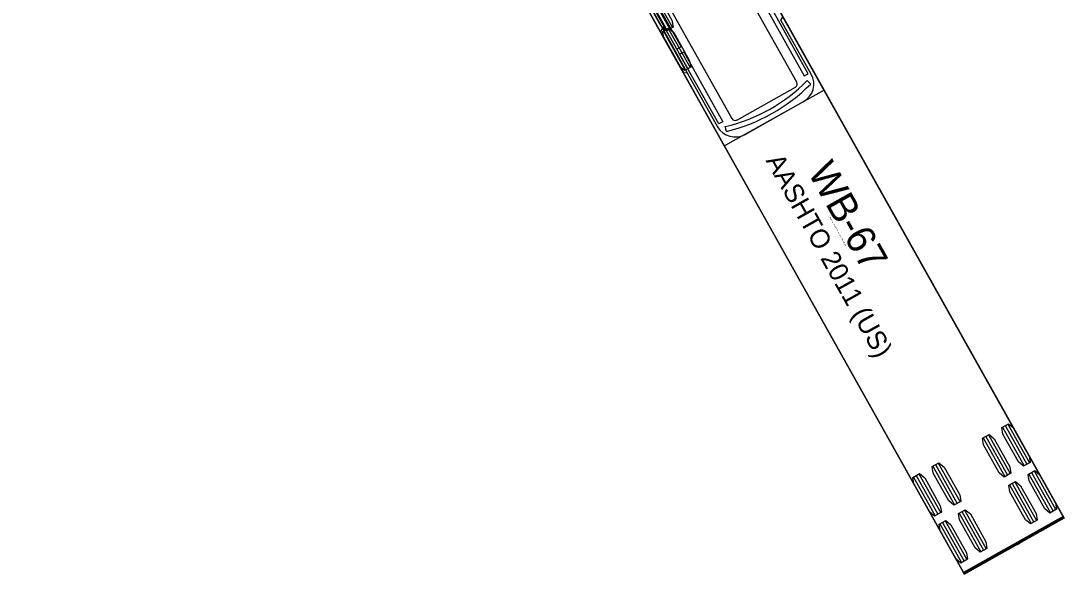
# Model space of a CAD drawing. Extents: x 1639988 to 1641860, y 841974 to 844187.
# Drawn here: x 1640559 to 1640636.6, y 843315.2 to 843356.3 of the extents above; entities that cross this region are included whole.
import ezdxf

# ---------------------------------------------------------------- set-up
doc = ezdxf.new("R2010")
doc.units = 0
for name, color, linetype in [('Scratch_Level_1', 7, 'Continuous'), ('Scratch_Level_2', 7, 'Continuous'), ('Scratch_Level_3', 7, 'Continuous'), ('Scratch_Level_4', 7, 'Continuous'), ('Scratch_Level_5', 7, 'Continuous'), ('Scratch_Level_6', 7, 'Continuous')]:
    doc.layers.add(name, color=color, linetype=linetype)

msp = doc.modelspace()

# ---------------------------------------------------------------- linework, layer by layer
at = {"layer": 'Scratch_Level_1'}
for p, q in [((1640605.299, 843358.802), (1640607.093, 843355.604)), ((1640605.499, 843358.914), (1640607.293, 843355.717)), ((1640605.699, 843359.026), (1640607.493, 843355.829)), ((1640632.043, 843326.126), (1640633.658, 843323.248)), ((1640632.243, 843326.238), (1640633.857, 843323.36)), ((1640632.442, 843326.35), (1640634.057, 843323.472)), ((1640630.604, 843325.319), (1640632.219, 843322.441)), ((1640630.804, 843325.431), (1640632.418, 843322.553)), ((1640631.003, 843325.543), (1640632.618, 843322.665)), ((1640626.868, 843323.223), (1640628.483, 843320.345)), ((1640627.068, 843323.335), (1640628.683, 843320.457)), ((1640627.268, 843323.447), (1640628.883, 843320.569)), ((1640634.2, 843322.75), (1640635.815, 843319.872)), ((1640634.4, 843322.862), (1640636.015, 843319.984)), ((1640625.429, 843322.415), (1640627.044, 843319.537)), ((1640625.629, 843322.527), (1640627.244, 843319.649)), ((1640625.829, 843322.639), (1640627.444, 843319.762)), ((1640632.961, 843322.055), (1640634.576, 843319.177)), ((1640634, 843322.638), (1640635.615, 843319.76)), ((1640632.561, 843321.83), (1640634.176, 843318.952)), ((1640632.761, 843321.942), (1640634.376, 843319.064)), ((1640628.826, 843319.734), (1640630.44, 843316.856)), ((1640629.026, 843319.846), (1640630.64, 843316.968)), ((1640629.225, 843319.959), (1640630.84, 843317.081)), ((1640627.387, 843318.927), (1640629.002, 843316.049)), ((1640627.587, 843319.039), (1640629.201, 843316.161)), ((1640627.786, 843319.151), (1640629.401, 843316.273)), ((1640636.561, 843319.478), (1640629.149, 843315.319)), ((1640632.889, 843317.337), (1640632.855, 843317.398)), ((1640633.353, 843317.597), (1640633.121, 843317.467)), ((1640632.658, 843317.207), (1640632.426, 843317.077))]:
    msp.add_line(p, q, dxfattribs=at)
for points in [[(1640569.35, 843442.491), (1640571.641, 843437.743), (1640573.976, 843433.013), (1640576.351, 843428.298), (1640578.765, 843423.598), (1640581.214, 843418.911), (1640583.696, 843414.235), (1640586.206, 843409.569), (1640588.742, 843404.91), (1640593.874, 843395.608), (1640599.062, 843386.314), (1640636.63, 843319.355), (1640629.218, 843315.196), (1640629.14, 843315.333), (1640629.14, 843315.333)], [(1640629.14, 843315.333), (1640571.712, 843417.686), (1640569.11, 843422.364), (1640566.534, 843427.059), (1640563.994, 843431.777), (1640560.226, 843438.882)], [(1640636.576, 843319.405), (1640636.595, 843319.416), (1640636.561, 843319.478), (1640633.788, 843324.42), (1640610.695, 843365.576), (1640606.989, 843363.496), (1640603.283, 843361.416), (1640626.375, 843320.261), (1640629.149, 843315.319), (1640629.184, 843315.257), (1640629.203, 843315.268)], [(1640633.153, 843317.404), (1640633.386, 843317.534), (1640633.387, 843317.536), (1640633.353, 843317.597), (1640633.384, 843317.614), (1640636.554, 843319.393), (1640636.555, 843319.394)], [(1640632.664, 843317.21), (1640633.118, 843317.465)], [(1640629.224, 843315.28), (1640629.224, 843315.28), (1640632.395, 843317.059), (1640632.426, 843317.077), (1640632.46, 843317.016), (1640632.462, 843317.016), (1640632.695, 843317.147)]]:
    msp.add_lwpolyline(points, dxfattribs=at)
for points in [[(1640605.249, 843358.774), (1640605.748, 843359.054), (1640606.15, 843358.691), (1640607.442, 843356.388), (1640607.542, 843355.856), (1640607.044, 843355.577), (1640606.642, 843355.94), (1640605.35, 843358.242)], [(1640631.993, 843326.098), (1640632.492, 843326.378), (1640632.868, 843326.06), (1640634.031, 843323.987), (1640634.107, 843323.5), (1640633.608, 843323.22), (1640633.232, 843323.539), (1640632.069, 843325.611)], [(1640630.554, 843325.291), (1640631.053, 843325.571), (1640631.429, 843325.252), (1640632.592, 843323.18), (1640632.668, 843322.693), (1640632.169, 843322.413), (1640631.793, 843322.731), (1640630.63, 843324.804)], [(1640626.819, 843323.195), (1640627.318, 843323.475), (1640627.694, 843323.156), (1640628.857, 843321.084), (1640628.932, 843320.597), (1640628.434, 843320.317), (1640628.057, 843320.635), (1640626.895, 843322.708)], [(1640633.951, 843322.61), (1640634.449, 843322.89), (1640634.826, 843322.571), (1640635.988, 843320.499), (1640636.064, 843320.012), (1640635.565, 843319.732), (1640635.189, 843320.051), (1640634.026, 843322.123)], [(1640625.38, 843322.387), (1640625.879, 843322.667), (1640626.255, 843322.349), (1640627.418, 843320.277), (1640627.493, 843319.789), (1640626.995, 843319.509), (1640626.618, 843319.828), (1640625.456, 843321.9)], [(1640632.512, 843321.802), (1640633.01, 843322.082), (1640633.387, 843321.764), (1640634.549, 843319.692), (1640634.625, 843319.204), (1640634.126, 843318.925), (1640633.75, 843319.243), (1640632.587, 843321.315)], [(1640628.776, 843319.706), (1640629.275, 843319.986), (1640629.651, 843319.668), (1640630.814, 843317.596), (1640630.89, 843317.108), (1640630.391, 843316.829), (1640630.015, 843317.147), (1640628.852, 843319.219)], [(1640627.337, 843318.899), (1640627.836, 843319.179), (1640628.212, 843318.86), (1640629.375, 843316.788), (1640629.451, 843316.301), (1640628.952, 843316.021), (1640628.576, 843316.34), (1640627.413, 843318.412)]]:
    msp.add_lwpolyline(points, close=True, dxfattribs=at)
for centre in [(1640636.583, 843319.37), (1640629.23, 843315.244)]:
    msp.add_circle(centre, 0.0266, dxfattribs=at)
for centre, radius, start, end in [((1640637.566, 843317.642), 2.022, 119.29724, 119.981), ((1640633.136, 843317.435), 0.0352, 120.27156, 299.27197), ((1640633.136, 843317.435), 0.0354, 303.58877, 115.77424), ((1640632.677, 843317.177), 0.0353, 122.63341, 300.98307), ((1640632.677, 843317.177), 0.0352, 299.3225, 118.32291), ((1640629.23, 843315.244), 0.0363, 138.37468, 99.53603)]:
    msp.add_arc(centre, radius, start, end, dxfattribs=at)
at = {"layer": 'Scratch_Level_2'}
for p, q in [((1640605.299, 843358.802), (1640607.093, 843355.604)), ((1640605.499, 843358.914), (1640607.293, 843355.717)), ((1640605.699, 843359.026), (1640607.493, 843355.829)), ((1640632.043, 843326.126), (1640633.658, 843323.248)), ((1640632.243, 843326.238), (1640633.857, 843323.36)), ((1640632.442, 843326.35), (1640634.057, 843323.472)), ((1640630.604, 843325.319), (1640632.219, 843322.441)), ((1640630.804, 843325.431), (1640632.418, 843322.553)), ((1640631.003, 843325.543), (1640632.618, 843322.665)), ((1640626.868, 843323.223), (1640628.483, 843320.345)), ((1640627.068, 843323.335), (1640628.683, 843320.457)), ((1640627.268, 843323.447), (1640628.883, 843320.569)), ((1640634.2, 843322.75), (1640635.815, 843319.872)), ((1640634.4, 843322.862), (1640636.015, 843319.984)), ((1640625.429, 843322.415), (1640627.044, 843319.537)), ((1640625.629, 843322.527), (1640627.244, 843319.649)), ((1640625.829, 843322.639), (1640627.444, 843319.762)), ((1640632.961, 843322.055), (1640634.576, 843319.177)), ((1640634, 843322.638), (1640635.615, 843319.76)), ((1640632.561, 843321.83), (1640634.176, 843318.952)), ((1640632.761, 843321.942), (1640634.376, 843319.064)), ((1640628.826, 843319.734), (1640630.44, 843316.856)), ((1640629.026, 843319.846), (1640630.64, 843316.968)), ((1640629.225, 843319.959), (1640630.84, 843317.081)), ((1640627.387, 843318.927), (1640629.002, 843316.049)), ((1640627.587, 843319.039), (1640629.201, 843316.161)), ((1640627.786, 843319.151), (1640629.401, 843316.273)), ((1640636.561, 843319.478), (1640629.149, 843315.319)), ((1640632.889, 843317.337), (1640632.855, 843317.398)), ((1640633.353, 843317.597), (1640633.121, 843317.467)), ((1640632.658, 843317.207), (1640632.426, 843317.077))]:
    msp.add_line(p, q, dxfattribs=at)
for points in [[(1640569.35, 843442.491), (1640571.641, 843437.743), (1640573.976, 843433.013), (1640576.351, 843428.298), (1640578.765, 843423.598), (1640581.214, 843418.911), (1640583.696, 843414.235), (1640586.206, 843409.569), (1640588.742, 843404.91), (1640593.874, 843395.608), (1640599.062, 843386.314), (1640636.63, 843319.355), (1640629.218, 843315.196), (1640629.144, 843315.327), (1640629.144, 843315.327)], [(1640629.144, 843315.327), (1640571.712, 843417.686), (1640569.11, 843422.364), (1640566.534, 843427.059), (1640563.994, 843431.777), (1640560.226, 843438.882)], [(1640636.576, 843319.405), (1640636.595, 843319.416), (1640636.561, 843319.478), (1640633.788, 843324.42), (1640610.695, 843365.576), (1640606.989, 843363.496), (1640603.283, 843361.416), (1640626.375, 843320.261), (1640629.149, 843315.319), (1640629.184, 843315.257), (1640629.203, 843315.268)], [(1640633.153, 843317.404), (1640633.386, 843317.534), (1640633.387, 843317.536), (1640633.353, 843317.597), (1640633.384, 843317.614), (1640636.554, 843319.393), (1640636.555, 843319.394)], [(1640632.664, 843317.21), (1640633.118, 843317.465)], [(1640629.224, 843315.28), (1640629.224, 843315.28), (1640632.395, 843317.059), (1640632.426, 843317.077), (1640632.46, 843317.016), (1640632.462, 843317.016), (1640632.695, 843317.147)]]:
    msp.add_lwpolyline(points, dxfattribs=at)
for points in [[(1640605.249, 843358.774), (1640605.748, 843359.054), (1640606.15, 843358.691), (1640607.442, 843356.388), (1640607.542, 843355.856), (1640607.044, 843355.577), (1640606.642, 843355.94), (1640605.35, 843358.242)], [(1640631.993, 843326.098), (1640632.492, 843326.378), (1640632.868, 843326.06), (1640634.031, 843323.987), (1640634.107, 843323.5), (1640633.608, 843323.22), (1640633.232, 843323.539), (1640632.069, 843325.611)], [(1640630.554, 843325.291), (1640631.053, 843325.571), (1640631.429, 843325.252), (1640632.592, 843323.18), (1640632.668, 843322.693), (1640632.169, 843322.413), (1640631.793, 843322.731), (1640630.63, 843324.804)], [(1640626.819, 843323.195), (1640627.318, 843323.475), (1640627.694, 843323.156), (1640628.857, 843321.084), (1640628.932, 843320.597), (1640628.434, 843320.317), (1640628.057, 843320.635), (1640626.895, 843322.708)], [(1640633.951, 843322.61), (1640634.449, 843322.89), (1640634.826, 843322.571), (1640635.988, 843320.499), (1640636.064, 843320.012), (1640635.565, 843319.732), (1640635.189, 843320.051), (1640634.026, 843322.123)], [(1640625.38, 843322.387), (1640625.879, 843322.667), (1640626.255, 843322.349), (1640627.418, 843320.277), (1640627.493, 843319.789), (1640626.995, 843319.509), (1640626.618, 843319.828), (1640625.456, 843321.9)], [(1640632.512, 843321.802), (1640633.01, 843322.082), (1640633.387, 843321.764), (1640634.549, 843319.692), (1640634.625, 843319.204), (1640634.126, 843318.925), (1640633.75, 843319.243), (1640632.587, 843321.315)], [(1640628.776, 843319.706), (1640629.275, 843319.986), (1640629.651, 843319.668), (1640630.814, 843317.596), (1640630.89, 843317.108), (1640630.391, 843316.829), (1640630.015, 843317.147), (1640628.852, 843319.219)], [(1640627.337, 843318.899), (1640627.836, 843319.179), (1640628.212, 843318.86), (1640629.375, 843316.788), (1640629.451, 843316.301), (1640628.952, 843316.021), (1640628.576, 843316.34), (1640627.413, 843318.412)]]:
    msp.add_lwpolyline(points, close=True, dxfattribs=at)
for centre in [(1640636.583, 843319.37), (1640629.23, 843315.244)]:
    msp.add_circle(centre, 0.0266, dxfattribs=at)
for centre, radius, start, end in [((1640637.566, 843317.642), 2.022, 119.29724, 119.981), ((1640633.136, 843317.435), 0.0352, 120.27156, 299.27197), ((1640633.136, 843317.435), 0.0354, 303.58877, 115.77424), ((1640632.677, 843317.177), 0.0353, 122.63341, 300.98307), ((1640632.677, 843317.177), 0.0352, 299.3225, 118.32291), ((1640629.23, 843315.244), 0.0363, 138.37468, 99.53603)]:
    msp.add_arc(centre, radius, start, end, dxfattribs=at)
at = {"layer": 'Scratch_Level_3'}
for p, q in [((1640605.299, 843358.802), (1640607.093, 843355.604)), ((1640605.499, 843358.914), (1640607.293, 843355.717)), ((1640605.699, 843359.026), (1640607.493, 843355.829)), ((1640632.043, 843326.126), (1640633.658, 843323.248)), ((1640632.243, 843326.238), (1640633.857, 843323.36)), ((1640632.442, 843326.35), (1640634.057, 843323.472)), ((1640630.604, 843325.319), (1640632.219, 843322.441)), ((1640630.804, 843325.431), (1640632.418, 843322.553)), ((1640631.003, 843325.543), (1640632.618, 843322.665)), ((1640626.868, 843323.223), (1640628.483, 843320.345)), ((1640627.068, 843323.335), (1640628.683, 843320.457)), ((1640627.268, 843323.447), (1640628.883, 843320.569)), ((1640634.2, 843322.75), (1640635.815, 843319.872)), ((1640634.4, 843322.862), (1640636.015, 843319.984)), ((1640625.429, 843322.415), (1640627.044, 843319.537)), ((1640625.629, 843322.527), (1640627.244, 843319.649)), ((1640625.829, 843322.639), (1640627.444, 843319.762)), ((1640632.961, 843322.055), (1640634.576, 843319.177)), ((1640634, 843322.638), (1640635.615, 843319.76)), ((1640632.561, 843321.83), (1640634.176, 843318.952)), ((1640632.761, 843321.942), (1640634.376, 843319.064)), ((1640628.826, 843319.734), (1640630.44, 843316.856)), ((1640629.026, 843319.846), (1640630.64, 843316.968)), ((1640629.225, 843319.959), (1640630.84, 843317.081)), ((1640627.387, 843318.927), (1640629.002, 843316.049)), ((1640627.587, 843319.039), (1640629.201, 843316.161)), ((1640627.786, 843319.151), (1640629.401, 843316.273)), ((1640636.561, 843319.478), (1640629.149, 843315.319)), ((1640632.889, 843317.337), (1640632.855, 843317.398)), ((1640633.353, 843317.597), (1640633.121, 843317.467)), ((1640632.658, 843317.207), (1640632.426, 843317.077))]:
    msp.add_line(p, q, dxfattribs=at)
for points in [[(1640569.35, 843442.491), (1640571.641, 843437.743), (1640573.976, 843433.013), (1640576.351, 843428.298), (1640578.765, 843423.598), (1640581.214, 843418.911), (1640583.696, 843414.235), (1640586.206, 843409.569), (1640588.742, 843404.91), (1640593.874, 843395.608), (1640599.062, 843386.314), (1640636.63, 843319.355), (1640629.218, 843315.196), (1640629.149, 843315.318), (1640629.149, 843315.318)], [(1640629.149, 843315.318), (1640571.712, 843417.686), (1640569.11, 843422.364), (1640566.534, 843427.059), (1640563.994, 843431.777), (1640560.226, 843438.882)], [(1640636.576, 843319.405), (1640636.595, 843319.416), (1640636.561, 843319.478), (1640633.788, 843324.42), (1640610.695, 843365.576), (1640606.989, 843363.496), (1640603.283, 843361.416), (1640626.375, 843320.261), (1640629.149, 843315.319), (1640629.184, 843315.257), (1640629.203, 843315.268)], [(1640633.153, 843317.404), (1640633.386, 843317.534), (1640633.387, 843317.536), (1640633.353, 843317.597), (1640633.384, 843317.614), (1640636.554, 843319.393), (1640636.555, 843319.394)], [(1640632.664, 843317.21), (1640633.118, 843317.465)], [(1640629.224, 843315.28), (1640629.224, 843315.28), (1640632.395, 843317.059), (1640632.426, 843317.077), (1640632.46, 843317.016), (1640632.462, 843317.016), (1640632.695, 843317.147)]]:
    msp.add_lwpolyline(points, dxfattribs=at)
for points in [[(1640605.249, 843358.774), (1640605.748, 843359.054), (1640606.15, 843358.691), (1640607.442, 843356.388), (1640607.542, 843355.856), (1640607.044, 843355.577), (1640606.642, 843355.94), (1640605.35, 843358.242)], [(1640631.993, 843326.098), (1640632.492, 843326.378), (1640632.868, 843326.06), (1640634.031, 843323.987), (1640634.107, 843323.5), (1640633.608, 843323.22), (1640633.232, 843323.539), (1640632.069, 843325.611)], [(1640630.554, 843325.291), (1640631.053, 843325.571), (1640631.429, 843325.252), (1640632.592, 843323.18), (1640632.668, 843322.693), (1640632.169, 843322.413), (1640631.793, 843322.731), (1640630.63, 843324.804)], [(1640626.819, 843323.195), (1640627.318, 843323.475), (1640627.694, 843323.156), (1640628.857, 843321.084), (1640628.932, 843320.597), (1640628.434, 843320.317), (1640628.057, 843320.635), (1640626.895, 843322.708)], [(1640633.951, 843322.61), (1640634.449, 843322.89), (1640634.826, 843322.571), (1640635.988, 843320.499), (1640636.064, 843320.012), (1640635.565, 843319.732), (1640635.189, 843320.051), (1640634.026, 843322.123)], [(1640625.38, 843322.387), (1640625.879, 843322.667), (1640626.255, 843322.349), (1640627.418, 843320.277), (1640627.493, 843319.789), (1640626.995, 843319.509), (1640626.618, 843319.828), (1640625.456, 843321.9)], [(1640632.512, 843321.802), (1640633.01, 843322.082), (1640633.387, 843321.764), (1640634.549, 843319.692), (1640634.625, 843319.204), (1640634.126, 843318.925), (1640633.75, 843319.243), (1640632.587, 843321.315)], [(1640628.776, 843319.706), (1640629.275, 843319.986), (1640629.651, 843319.668), (1640630.814, 843317.596), (1640630.89, 843317.108), (1640630.391, 843316.829), (1640630.015, 843317.147), (1640628.852, 843319.219)], [(1640627.337, 843318.899), (1640627.836, 843319.179), (1640628.212, 843318.86), (1640629.375, 843316.788), (1640629.451, 843316.301), (1640628.952, 843316.021), (1640628.576, 843316.34), (1640627.413, 843318.412)]]:
    msp.add_lwpolyline(points, close=True, dxfattribs=at)
for centre in [(1640636.583, 843319.37), (1640629.23, 843315.244)]:
    msp.add_circle(centre, 0.0266, dxfattribs=at)
for centre, radius, start, end in [((1640637.566, 843317.642), 2.022, 119.29724, 119.981), ((1640633.136, 843317.435), 0.0352, 120.27156, 299.27197), ((1640633.136, 843317.435), 0.0354, 303.58877, 115.77424), ((1640632.677, 843317.177), 0.0353, 122.63341, 300.98307), ((1640632.677, 843317.177), 0.0352, 299.3225, 118.32291), ((1640629.23, 843315.244), 0.0363, 138.37468, 99.53603)]:
    msp.add_arc(centre, radius, start, end, dxfattribs=at)
at = {"layer": 'Scratch_Level_4'}
for p, q in [((1640616.744, 843351.77), (1640598.916, 843383.542)), ((1640594.087, 843380.832), (1640611.914, 843349.06)), ((1640606.735, 843355.778), (1640608.587, 843352.475)), ((1640606.808, 843355.559), (1640608.439, 843352.652)), ((1640606.99, 843355.661), (1640608.621, 843352.754)), ((1640607.171, 843355.763), (1640608.803, 843352.856)), ((1640612.282, 843348.956), (1640616.641, 843351.402))]:
    msp.add_line(p, q, dxfattribs=at)
for points in [[(1640611.208, 843347.292), (1640590.328, 843384.504), (1640574.652, 843412.392), (1640569.434, 843421.74), (1640561.561, 843435.788), (1640560.271, 843438.147), (1640559.001, 843440.517)], [(1640569.265, 843440.462), (1640571.686, 843435.764), (1640574.153, 843431.085), (1640576.662, 843426.421), (1640579.206, 843421.768), (1640584.378, 843412.479), (1640618.769, 843351.186), (1640611.357, 843347.027), (1640611.208, 843347.292), (1640611.208, 843347.292)], [(1640617.816, 843352.371), (1640615.562, 843356.389), (1640615.711, 843356.637), (1640613.998, 843359.689), (1640613.709, 843359.691), (1640603.407, 843378.051), (1640603.478, 843378.439), (1640601.765, 843381.491), (1640601.397, 843381.633)], [(1640593.014, 843380.23), (1640594.423, 843377.72), (1640594.352, 843377.332), (1640596.065, 843374.28), (1640596.433, 843374.138), (1640606.735, 843355.778), (1640606.586, 843355.53), (1640608.298, 843352.477), (1640608.587, 843352.475), (1640610.842, 843348.458)], [(1640617.51, 843351.881), (1640617.771, 843351.631)], [(1640612.884, 843347.884), (1640617.242, 843350.329)], [(1640611.497, 843348.111), (1640611.42, 843348.464)]]:
    msp.add_lwpolyline(points, dxfattribs=at)
for points in [[(1640608.122, 843354.385), (1640607.821, 843354.216), (1640604.905, 843359.414), (1640605.206, 843359.582)], [(1640617.291, 843352.228), (1640617.592, 843352.396), (1640614.676, 843357.594), (1640614.375, 843357.424)], [(1640606.763, 843355.534), (1640607.217, 843355.788), (1640607.581, 843355.458), (1640608.756, 843353.365), (1640608.848, 843352.881), (1640608.394, 843352.627), (1640608.029, 843352.957), (1640606.855, 843355.05)], [(1640611.238, 843348.831), (1640610.937, 843348.662), (1640608.021, 843353.86), (1640608.322, 843354.028)]]:
    msp.add_lwpolyline(points, close=True, dxfattribs=at)
for centre, radius, start, end in [((1640616.508, 843351.637), 1.5, 299.29724, 29.29724), ((1640608.484, 843360.831), 12.711, 283.35448, 315.23999), ((1640608.484, 843360.831), 13.073, 283.3243, 315.27017), ((1640616.508, 843351.637), 0.27, 299.29724, 29.29724), ((1640612.15, 843349.192), 1.5, 209.29724, 299.29724), ((1640612.15, 843349.192), 0.27, 209.29724, 299.29724)]:
    msp.add_arc(centre, radius, start, end, dxfattribs=at)
at = {"layer": 'Scratch_Level_5'}
for p, q in [((1640616.744, 843351.77), (1640598.916, 843383.542)), ((1640594.087, 843380.832), (1640611.914, 843349.06)), ((1640606.735, 843355.778), (1640608.587, 843352.475)), ((1640606.808, 843355.559), (1640608.439, 843352.652)), ((1640606.99, 843355.661), (1640608.621, 843352.754)), ((1640607.171, 843355.763), (1640608.803, 843352.856)), ((1640612.282, 843348.956), (1640616.641, 843351.402))]:
    msp.add_line(p, q, dxfattribs=at)
for points in [[(1640611.214, 843347.281), (1640590.328, 843384.504), (1640574.652, 843412.392), (1640569.434, 843421.74), (1640561.561, 843435.788), (1640560.271, 843438.147), (1640559.001, 843440.517)], [(1640569.265, 843440.462), (1640571.686, 843435.764), (1640574.153, 843431.085), (1640576.662, 843426.421), (1640579.206, 843421.768), (1640584.378, 843412.479), (1640618.769, 843351.186), (1640611.357, 843347.027), (1640611.214, 843347.281), (1640611.214, 843347.281)], [(1640617.816, 843352.371), (1640615.562, 843356.389), (1640615.711, 843356.637), (1640613.998, 843359.689), (1640613.709, 843359.691), (1640603.407, 843378.051), (1640603.478, 843378.439), (1640601.765, 843381.491), (1640601.397, 843381.633)], [(1640593.014, 843380.23), (1640594.423, 843377.72), (1640594.352, 843377.332), (1640596.065, 843374.28), (1640596.433, 843374.138), (1640606.735, 843355.778), (1640606.586, 843355.53), (1640608.298, 843352.477), (1640608.587, 843352.475), (1640610.842, 843348.458)], [(1640617.51, 843351.881), (1640617.771, 843351.631)], [(1640612.884, 843347.884), (1640617.242, 843350.329)], [(1640611.497, 843348.111), (1640611.42, 843348.464)]]:
    msp.add_lwpolyline(points, dxfattribs=at)
for points in [[(1640608.122, 843354.385), (1640607.821, 843354.216), (1640604.905, 843359.414), (1640605.206, 843359.582)], [(1640617.291, 843352.228), (1640617.592, 843352.396), (1640614.676, 843357.594), (1640614.375, 843357.424)], [(1640606.763, 843355.534), (1640607.217, 843355.788), (1640607.581, 843355.458), (1640608.756, 843353.365), (1640608.848, 843352.881), (1640608.394, 843352.627), (1640608.029, 843352.957), (1640606.855, 843355.05)], [(1640611.238, 843348.831), (1640610.937, 843348.662), (1640608.021, 843353.86), (1640608.322, 843354.028)]]:
    msp.add_lwpolyline(points, close=True, dxfattribs=at)
for centre, radius, start, end in [((1640616.508, 843351.637), 1.5, 299.29724, 29.29724), ((1640608.484, 843360.831), 12.711, 283.35448, 315.23999), ((1640608.484, 843360.831), 13.073, 283.3243, 315.27017), ((1640616.508, 843351.637), 0.27, 299.29724, 29.29724), ((1640612.15, 843349.192), 1.5, 209.29724, 299.29724), ((1640612.15, 843349.192), 0.27, 209.29724, 299.29724)]:
    msp.add_arc(centre, radius, start, end, dxfattribs=at)
at = {"layer": 'Scratch_Level_6'}
for p, q in [((1640616.744, 843351.77), (1640598.916, 843383.542)), ((1640594.087, 843380.832), (1640611.914, 843349.06)), ((1640606.735, 843355.778), (1640608.587, 843352.475)), ((1640606.808, 843355.559), (1640608.439, 843352.652)), ((1640606.99, 843355.661), (1640608.621, 843352.754)), ((1640607.171, 843355.763), (1640608.803, 843352.856)), ((1640612.282, 843348.956), (1640616.641, 843351.402))]:
    msp.add_line(p, q, dxfattribs=at)
for points in [[(1640611.238, 843347.239), (1640590.328, 843384.504), (1640574.652, 843412.392), (1640569.434, 843421.74), (1640561.561, 843435.788), (1640560.271, 843438.147), (1640559.001, 843440.517)], [(1640569.265, 843440.462), (1640571.686, 843435.764), (1640574.153, 843431.085), (1640576.662, 843426.421), (1640579.206, 843421.768), (1640584.378, 843412.479), (1640618.769, 843351.186), (1640611.357, 843347.027), (1640611.238, 843347.239), (1640611.238, 843347.239)], [(1640617.816, 843352.371), (1640615.562, 843356.389), (1640615.711, 843356.637), (1640613.998, 843359.689), (1640613.709, 843359.691), (1640603.407, 843378.051), (1640603.478, 843378.439), (1640601.765, 843381.491), (1640601.397, 843381.633)], [(1640593.014, 843380.23), (1640594.423, 843377.72), (1640594.352, 843377.332), (1640596.065, 843374.28), (1640596.433, 843374.138), (1640606.735, 843355.778), (1640606.586, 843355.53), (1640608.298, 843352.477), (1640608.587, 843352.475), (1640610.842, 843348.458)], [(1640617.51, 843351.881), (1640617.771, 843351.631)], [(1640612.884, 843347.884), (1640617.242, 843350.329)], [(1640611.497, 843348.111), (1640611.42, 843348.464)]]:
    msp.add_lwpolyline(points, dxfattribs=at)
for points in [[(1640608.122, 843354.385), (1640607.821, 843354.216), (1640604.905, 843359.414), (1640605.206, 843359.582)], [(1640617.291, 843352.228), (1640617.592, 843352.396), (1640614.676, 843357.594), (1640614.375, 843357.424)], [(1640606.763, 843355.534), (1640607.217, 843355.788), (1640607.581, 843355.458), (1640608.756, 843353.365), (1640608.848, 843352.881), (1640608.394, 843352.627), (1640608.029, 843352.957), (1640606.855, 843355.05)], [(1640611.238, 843348.831), (1640610.937, 843348.662), (1640608.021, 843353.86), (1640608.322, 843354.028)]]:
    msp.add_lwpolyline(points, close=True, dxfattribs=at)
for centre, radius, start, end in [((1640616.508, 843351.637), 1.5, 299.29724, 29.29724), ((1640608.484, 843360.831), 12.711, 283.35448, 315.23999), ((1640608.484, 843360.831), 13.073, 283.3243, 315.27017), ((1640616.508, 843351.637), 0.27, 299.29724, 29.29724), ((1640612.15, 843349.192), 1.5, 209.29724, 299.29724), ((1640612.15, 843349.192), 0.27, 209.29724, 299.29724)]:
    msp.add_arc(centre, radius, start, end, dxfattribs=at)

# ---------------------------------------------------------------- texts
at = {"layer": 'Scratch_Level_1'}
for s, height, p in [('AASHTO 2011 (US)', 1.41667, (1640614.396, 843345.939)), ('WB-67', 2.125, (1640617.505, 843345.102)), ('(c) 2019 Transoft Solutions, Inc. All rights reserved.', 0.085, (1640619.072, 843341.876))]:
    msp.add_text(s, height=height, rotation=299.29724, dxfattribs=at).set_placement(p)
at = {"layer": 'Scratch_Level_2'}
for s, height, p in [('AASHTO 2011 (US)', 1.41667, (1640614.396, 843345.939)), ('WB-67', 2.125, (1640617.505, 843345.102)), ('(c) 2019 Transoft Solutions, Inc. All rights reserved.', 0.085, (1640619.072, 843341.876))]:
    msp.add_text(s, height=height, rotation=299.29724, dxfattribs=at).set_placement(p)
at = {"layer": 'Scratch_Level_3'}
for s, height, p in [('AASHTO 2011 (US)', 1.41667, (1640614.396, 843345.939)), ('WB-67', 2.125, (1640617.505, 843345.102)), ('(c) 2019 Transoft Solutions, Inc. All rights reserved.', 0.085, (1640619.072, 843341.876))]:
    msp.add_text(s, height=height, rotation=299.29724, dxfattribs=at).set_placement(p)

doc.saveas('drawing.dxf')
